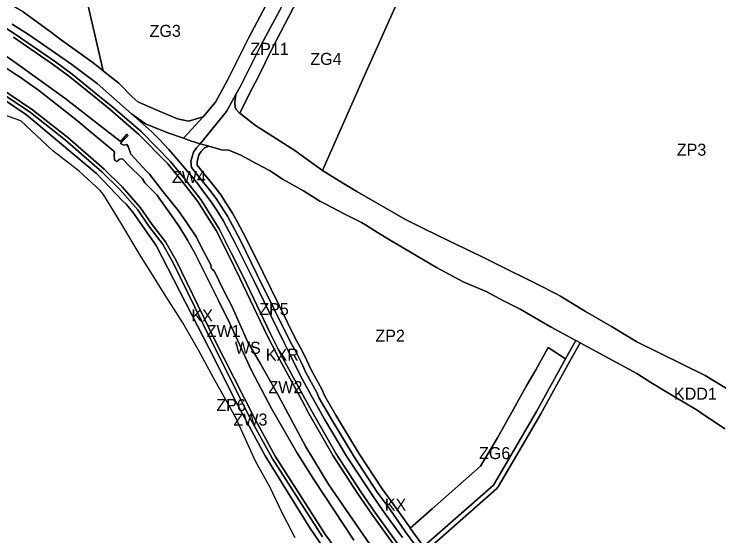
# Model space of a CAD drawing. Extents: x -297419 to -295590, y 31782 to 32981.
# Drawn here: x -296966 to -296379, y 32210 to 32644 of the extents above; entities that cross this region are included whole.
import ezdxf

# ---------------------------------------------------------------- set-up
doc = ezdxf.new("R2010")
doc.units = 0
doc.layers.add('linie_rozgraniczajace', color=7, linetype='Continuous')
doc.layers.add('oznaczenia_przeznaczen', color=7, linetype='Continuous')

msp = doc.modelspace()

# ---------------------------------------------------------------- linework, layer by layer
at = {"layer": 'linie_rozgraniczajace'}
for points in [[(-296976.44, 32861.62), (-296954.158, 32868.81), (-296944.683, 32827.94), (-296939.922, 32807.258), (-296932.119, 32773.36), (-296931.995, 32772.823), (-296926.966, 32750.975), (-296918.118, 32712.537), (-296891.531, 32597.037), (-296894.697, 32599.518), (-296901.08, 32604.52), (-296925.488, 32622.081), (-296927.25, 32623.39), (-296934.691, 32628.923), (-296957.75, 32645.71), (-296964.522, 32649.843), (-296968.384, 32652.199)], [(-296756.167, 32651.476), (-296770.737, 32624.238), (-296788.254, 32589.203), (-296798.128, 32570.931), (-296808.381, 32558.868), (-296820.475, 32555.248), (-296829.819, 32557.158), (-296845.48, 32563.71), (-296860.2, 32570.14), (-296862.84, 32571.4), (-296867.53, 32575.43), (-296878.57, 32586.88), (-296888.438, 32594.613), (-296891.531, 32597.037), (-296918.118, 32712.537)], [(-296362.44, 32326.55), (-296390.75, 32343.51), (-296447.62, 32371.53), (-296468.7, 32384.54), (-296490.15, 32396.76), (-296510.95, 32409.64), (-296514, 32411.185), (-296530.55, 32419.57), (-296562.45, 32435.41), (-296577.24, 32442.8), (-296603.9, 32455.7), (-296625.168, 32466.016), (-296640.53, 32473.71), (-296680.41, 32496.56), (-296691.574, 32503.211), (-296709.14, 32514.16), (-296675.16, 32590.56), (-296634.187, 32682.543)], [(-296744.618, 32647.626), (-296760.078, 32618.724), (-296777.535, 32583.808), (-296781.079, 32577.235), (-296788.984, 32563.16), (-296810.821, 32536.449), (-296818.119, 32538.537), (-296824.845, 32540.945), (-296808.381, 32558.868), (-296798.128, 32570.931), (-296788.254, 32589.203), (-296770.737, 32624.238), (-296756.167, 32651.476)], [(-296957.75, 32645.71), (-296934.691, 32628.923), (-296927.25, 32623.39), (-296925.488, 32622.081), (-296901.08, 32604.52), (-296894.697, 32599.518), (-296891.531, 32597.037), (-296888.438, 32594.613), (-296878.57, 32586.88), (-296867.53, 32575.43), (-296862.84, 32571.4), (-296860.2, 32570.14), (-296845.48, 32563.71), (-296829.819, 32557.158), (-296820.475, 32555.248), (-296808.381, 32558.868), (-296824.845, 32540.945), (-296837.731, 32545.558), (-296856.37, 32553.057), (-296868.02, 32561.4), (-296896.58, 32586.45), (-296917.7, 32602.32), (-296941.1, 32618.6), (-296953.84, 32627.24), (-296967.38, 32635.97)], [(-296646.165, 32203.209), (-296665.589, 32230.008), (-296677.227, 32246.762), (-296697.671, 32278.496), (-296717.798, 32313.354), (-296723.674, 32324.631), (-296743.675, 32361.05), (-296752.326, 32378.33), (-296775.102, 32426.026), (-296784.992, 32445.807), (-296794.94, 32465.703), (-296804.755, 32481.127), (-296810.39, 32489.981), (-296824.182, 32507.725), (-296835.451, 32521.617), (-296860.077, 32546.649), (-296883.508, 32566.906), (-296895.893, 32576.912), (-296917.46, 32594.338), (-296931.299, 32604.419), (-296964.677, 32627.527), (-296979.731, 32637)], [(-296979.731, 32637), (-296964.677, 32627.527), (-296931.299, 32604.419), (-296917.46, 32594.338), (-296895.893, 32576.912), (-296883.508, 32566.906), (-296860.077, 32546.649), (-296835.451, 32521.617), (-296824.182, 32507.725), (-296810.39, 32489.981), (-296804.755, 32481.127), (-296794.94, 32465.703), (-296784.992, 32445.807), (-296775.102, 32426.026), (-296752.326, 32378.33), (-296743.675, 32361.05), (-296723.674, 32324.631), (-296717.798, 32313.354), (-296697.671, 32278.496), (-296677.227, 32246.762), (-296665.589, 32230.008), (-296646.165, 32203.209)], [(-296967.38, 32635.97), (-296953.84, 32627.24), (-296941.1, 32618.6), (-296917.7, 32602.32), (-296896.58, 32586.45), (-296868.02, 32561.4), (-296853.82, 32548.89), (-296851.37, 32546.561), (-296844.87, 32540.28), (-296836.92, 32531.64), (-296825.29, 32518.08), (-296813.71, 32504.11), (-296806.86, 32495.16), (-296801.72, 32488.08), (-296796.66, 32480.63), (-296791.82, 32472.68), (-296781.88, 32453.75), (-296766.15, 32422.74), (-296753.13, 32395.9), (-296740.79, 32370.33), (-296736.62, 32362.06), (-296727.35, 32343.5), (-296719.17, 32328.01), (-296707.31, 32307.22), (-296689.12, 32276.56), (-296664.353, 32239.292), (-296656.947, 32228.497), (-296645.682, 32213.119), (-296642.579, 32208.932)], [(-296966.331, 32625.023), (-296933.037, 32601.973), (-296919.287, 32591.957), (-296897.778, 32574.579), (-296885.433, 32564.604), (-296862.131, 32544.458), (-296837.69, 32519.616), (-296826.531, 32505.859), (-296812.846, 32488.252), (-296807.286, 32479.516), (-296797.554, 32464.223), (-296787.676, 32444.466), (-296777.797, 32424.708), (-296755.021, 32377.012), (-296746.332, 32359.656), (-296726.319, 32323.216), (-296720.428, 32311.91), (-296700.232, 32276.933), (-296679.721, 32245.094), (-296668.036, 32228.272), (-296648.571, 32201.417)], [(-296648.571, 32201.417), (-296668.036, 32228.272), (-296679.721, 32245.094), (-296700.232, 32276.933), (-296720.428, 32311.91), (-296726.319, 32323.216), (-296746.332, 32359.656), (-296755.021, 32377.012), (-296777.797, 32424.708), (-296787.676, 32444.466), (-296797.554, 32464.223), (-296807.286, 32479.516), (-296812.846, 32488.252), (-296826.531, 32505.859), (-296837.69, 32519.616), (-296862.131, 32544.458), (-296885.433, 32564.604), (-296897.778, 32574.579), (-296919.287, 32591.957), (-296933.037, 32601.973), (-296966.331, 32625.023)], [(-296979.7, 32614.244), (-296963.992, 32603.349), (-296923.496, 32574.312), (-296889.742, 32547.865), (-296877.351, 32538.498), (-296876.147, 32539.441), (-296871.887, 32544.352), (-296870.704, 32543.326), (-296875.822, 32538.368), (-296876.433, 32537.776), (-296877.221, 32536.547), (-296874.513, 32535.156), (-296872.017, 32535.831), (-296870.683, 32534.238), (-296868.7, 32527.668), (-296855.755, 32513.911), (-296853.14, 32511.131), (-296841.575, 32496.544), (-296828.794, 32480.705), (-296821.867, 32470.493), (-296814.061, 32458.622), (-296810.256, 32451.223), (-296801.67, 32435.238), (-296801.941, 32434.181), (-296800.499, 32431.303), (-296799.556, 32431.205), (-296790.775, 32413.513), (-296784.189, 32400.682), (-296771.537, 32371.883), (-296760.707, 32353.345), (-296746.366, 32327.729), (-296722.887, 32284.284), (-296703.71, 32252.679), (-296670.068, 32203.65)], [(-296670.068, 32203.65), (-296703.71, 32252.679), (-296722.887, 32284.284), (-296746.366, 32327.729), (-296760.707, 32353.345), (-296771.537, 32371.883), (-296784.189, 32400.682), (-296790.775, 32413.513), (-296799.556, 32431.205), (-296800.499, 32431.303), (-296801.941, 32434.181), (-296801.67, 32435.238), (-296810.256, 32451.223), (-296814.061, 32458.622), (-296821.867, 32470.493), (-296828.794, 32480.705), (-296841.575, 32496.544), (-296853.14, 32511.131), (-296855.755, 32513.911), (-296868.7, 32527.668), (-296870.683, 32534.238), (-296872.017, 32535.831), (-296874.513, 32535.156), (-296877.221, 32536.547), (-296876.433, 32537.776), (-296875.822, 32538.368), (-296870.704, 32543.326), (-296871.887, 32544.352), (-296876.147, 32539.441), (-296877.351, 32538.498), (-296889.742, 32547.865), (-296923.496, 32574.312), (-296963.992, 32603.349), (-296979.7, 32614.244)], [(-296694.342, 32194.502), (-296706.643, 32211.054), (-296730.709, 32248.724), (-296748.443, 32276.481), (-296766.053, 32308.581), (-296799.127, 32374.145), (-296812.592, 32401.695), (-296830.965, 32439.291), (-296839.843, 32454.739), (-296851.191, 32469.491), (-296860.484, 32483.175), (-296875.558, 32500.298), (-296890.705, 32515.225), (-296921.073, 32541.568), (-296950.342, 32564.691), (-296997.759, 32596.595)], [(-296997.759, 32596.595), (-296950.342, 32564.691), (-296921.073, 32541.568), (-296890.705, 32515.225), (-296875.558, 32500.298), (-296860.484, 32483.175), (-296851.191, 32469.491), (-296839.843, 32454.739), (-296830.965, 32439.291), (-296812.592, 32401.695), (-296799.127, 32374.145), (-296766.053, 32308.581), (-296748.443, 32276.481), (-296730.709, 32248.724), (-296706.643, 32211.054), (-296694.342, 32194.502)], [(-296903.987, 32548.085), (-296913.049, 32555.48), (-296938.966, 32575.968), (-296945.263, 32580.972), (-296952.753, 32586.184), (-296961.537, 32592.263), (-296965.131, 32594.622), (-296972.482, 32599.629)], [(-296972.482, 32599.629), (-296965.131, 32594.622), (-296961.537, 32592.263), (-296952.753, 32586.184), (-296945.263, 32580.972), (-296938.966, 32575.968), (-296913.049, 32555.48), (-296903.987, 32548.085), (-296887.59, 32534.3), (-296882.698, 32530.239), (-296882.234, 32529.374), (-296882.353, 32527.237), (-296882.107, 32522.806), (-296880.203, 32521.685), (-296877.784, 32523.552), (-296875.635, 32523.782), (-296870.593, 32518.457), (-296858.821, 32507.292), (-296857.003, 32503.783), (-296853.835, 32500.806), (-296851.547, 32498.563), (-296846.542, 32493.615), (-296844.34, 32490.379), (-296834.598, 32476.753), (-296827.911, 32466.774), (-296821.393, 32456.15), (-296815.494, 32446.001), (-296796.259, 32407.061), (-296786.235, 32386.815), (-296768.036, 32347.909), (-296751.391, 32316.324), (-296730.434, 32279.724), (-296716.319, 32257.025), (-296682.955, 32206.55)], [(-296999.388, 32594.075), (-296952.112, 32562.266), (-296922.986, 32539.257), (-296892.743, 32513.021), (-296877.74, 32498.235), (-296862.86, 32481.334), (-296853.623, 32467.732), (-296842.344, 32453.07), (-296833.616, 32437.884), (-296815.287, 32400.378), (-296801.815, 32372.811), (-296768.708, 32307.183), (-296751.025, 32274.951), (-296733.238, 32247.109), (-296709.114, 32209.35)], [(-296709.114, 32209.35), (-296733.238, 32247.109), (-296751.025, 32274.951), (-296768.708, 32307.183), (-296801.815, 32372.811), (-296815.287, 32400.378), (-296833.616, 32437.884), (-296842.344, 32453.07), (-296853.623, 32467.732), (-296862.86, 32481.334), (-296877.74, 32498.235), (-296892.743, 32513.021), (-296922.986, 32539.257), (-296952.112, 32562.266), (-296999.388, 32594.075)], [(-296996.6, 32588.21), (-296956.31, 32561.08), (-296953.776, 32558.972), (-296928, 32537.52), (-296897.27, 32511.62), (-296875.179, 32488.725), (-296872.51, 32486.08), (-296866.97, 32479.53), (-296847.58, 32451.73), (-296803.26, 32365.99), (-296781.55, 32322.47), (-296756.9, 32276.76), (-296719.6, 32217.08), (-296700.61, 32188.99)], [(-296700.61, 32188.99), (-296719.6, 32217.08), (-296756.9, 32276.76), (-296781.55, 32322.47), (-296803.26, 32365.99), (-296847.58, 32451.73), (-296866.97, 32479.53), (-296872.51, 32486.08), (-296875.179, 32488.725), (-296897.27, 32511.62), (-296928, 32537.52), (-296953.776, 32558.972), (-296956.31, 32561.08), (-296996.6, 32588.21)], [(-296374.24, 32299.4), (-296394.44, 32312.98), (-296397.416, 32314.751), (-296424.062, 32330.514), (-296435.806, 32337.962), (-296447.55, 32345.41), (-296494.83, 32370.91), (-296498.355, 32372.801), (-296518.695, 32383.711), (-296544.62, 32398.85), (-296557.817, 32405.549), (-296572.89, 32413.46), (-296592.12, 32421.52), (-296614.14, 32433.58), (-296652.724, 32456.188), (-296663.209, 32462.514), (-296673.427, 32469.046), (-296676.747, 32470.782), (-296690.52, 32477.86), (-296706.981, 32486.44), (-296711.26, 32488.67), (-296724.99, 32497.22), (-296741.7, 32506.77), (-296753.12, 32514.09), (-296764.31, 32520.1), (-296777.12, 32526.87), (-296786.9, 32531.07), (-296793.139, 32531.392), (-296803.709, 32534.415), (-296810.821, 32536.449), (-296788.984, 32563.16), (-296781.079, 32577.235), (-296782.064, 32570.68), (-296781.704, 32566.441), (-296780.654, 32564.479), (-296778.499, 32562.184), (-296777.942, 32561.747), (-296764.83, 32551.46), (-296744.291, 32538.492), (-296732.02, 32530.79), (-296723.08, 32524.03), (-296709.14, 32514.16), (-296691.574, 32503.211), (-296680.41, 32496.56), (-296640.53, 32473.71), (-296625.168, 32466.016), (-296603.9, 32455.7), (-296577.24, 32442.8), (-296562.45, 32435.41), (-296530.55, 32419.57), (-296514, 32411.185), (-296510.95, 32409.64), (-296490.15, 32396.76), (-296468.7, 32384.54), (-296447.62, 32371.53), (-296390.75, 32343.51), (-296362.44, 32326.55)], [(-296731.83, 32208.6), (-296742.31, 32228.86), (-296752.59, 32250.4), (-296764.79, 32272.44), (-296780.64, 32307.22), (-296787.11, 32319.05), (-296799.85, 32341.69), (-296812.3, 32364.77), (-296825.39, 32387.55), (-296833.1, 32399.52), (-296840.03, 32410.55), (-296850.59, 32427.25), (-296860.06, 32442.35), (-296876.78, 32470.6), (-296891.23, 32494.12), (-296894.12, 32497.43), (-296911.59, 32513.59), (-296933.39, 32530.65), (-296960.04, 32555.36), (-296990.35, 32566.02)], [(-296642.579, 32208.932), (-296645.682, 32213.119), (-296656.947, 32228.497), (-296664.353, 32239.292), (-296689.12, 32276.56), (-296707.31, 32307.22), (-296719.17, 32328.01), (-296727.35, 32343.5), (-296736.62, 32362.06), (-296740.79, 32370.33), (-296753.13, 32395.9), (-296766.15, 32422.74), (-296781.88, 32453.75), (-296791.82, 32472.68), (-296796.66, 32480.63), (-296801.72, 32488.08), (-296806.86, 32495.16), (-296813.71, 32504.11), (-296825.29, 32518.08), (-296836.92, 32531.64), (-296844.87, 32540.28), (-296851.37, 32546.561), (-296853.82, 32548.89), (-296868.02, 32561.4), (-296856.37, 32553.057), (-296837.731, 32545.558), (-296824.845, 32540.945), (-296818.119, 32538.537), (-296810.821, 32536.449), (-296810.834, 32536.433), (-296814.004, 32533.133), (-296816.473, 32529.357), (-296818.326, 32522.673), (-296818.556, 32521.843), (-296818.101, 32516.592), (-296810.511, 32507.208), (-296804.285, 32499.47), (-296797.672, 32490.937), (-296793.22, 32483.862), (-296788.209, 32476.139), (-296784.239, 32468.853), (-296777.282, 32455.872), (-296763.349, 32427.307), (-296735.724, 32371.365), (-296730.62, 32362.481), (-296726.939, 32354.612), (-296722.942, 32346.058), (-296714.216, 32330.141), (-296711.916, 32324.823), (-296702.253, 32308.033), (-296682.71, 32275.902), (-296663.514, 32246.531), (-296653.68, 32233.27), (-296640.249, 32214.007), (-296628.751, 32198.069)], [(-296682.955, 32206.55), (-296716.319, 32257.025), (-296730.434, 32279.724), (-296751.391, 32316.324), (-296768.036, 32347.909), (-296786.235, 32386.815), (-296796.259, 32407.061), (-296815.494, 32446.001), (-296821.393, 32456.15), (-296827.911, 32466.774), (-296834.598, 32476.753), (-296844.34, 32490.379), (-296846.542, 32493.615), (-296851.547, 32498.563), (-296853.835, 32500.806), (-296857.003, 32503.783), (-296858.821, 32507.292), (-296870.593, 32518.457), (-296875.635, 32523.782), (-296877.784, 32523.552), (-296880.203, 32521.685), (-296882.107, 32522.806), (-296882.353, 32527.237), (-296882.234, 32529.374), (-296882.698, 32530.239), (-296887.59, 32534.3), (-296903.987, 32548.085)], [(-296818.556, 32521.843), (-296818.326, 32522.673), (-296816.473, 32529.357), (-296814.004, 32533.133), (-296810.834, 32536.433), (-296810.821, 32536.449), (-296803.709, 32534.415), (-296807.228, 32532.97), (-296810.075, 32530.006), (-296811.862, 32527.272), (-296813.497, 32521.376), (-296813.251, 32518.547), (-296806.615, 32510.343), (-296800.361, 32502.569), (-296793.72, 32494), (-296789.01, 32486.56), (-296783.91, 32478.7), (-296779.84, 32471.23), (-296772.83, 32458.15), (-296758.86, 32429.51), (-296731.31, 32373.72), (-296726.18, 32364.79), (-296722.41, 32356.73), (-296718.48, 32348.32), (-296709.72, 32332.34), (-296707.44, 32327.07), (-296697.95, 32310.58), (-296678.48, 32278.57), (-296659.41, 32249.39), (-296649.62, 32236.19), (-296636.17, 32216.9), (-296636.097, 32216.799), (-296624.981, 32201.389), (-296566.937, 32252.512), (-296566.047, 32253.693), (-296554.264, 32273.86), (-296530.986, 32313.692), (-296506.9, 32357.447), (-296498.355, 32372.801), (-296494.83, 32370.91), (-296503.4, 32355.51), (-296527.507, 32311.718), (-296550.81, 32271.842), (-296562.712, 32251.472), (-296563.988, 32249.779), (-296622.63, 32198.13)], [(-296726.939, 32354.612), (-296730.62, 32362.481), (-296735.724, 32371.365), (-296763.349, 32427.307), (-296777.282, 32455.872), (-296784.239, 32468.853), (-296788.209, 32476.139), (-296793.22, 32483.862), (-296797.672, 32490.937), (-296804.285, 32499.47), (-296810.511, 32507.208), (-296818.101, 32516.592), (-296818.556, 32521.843)], [(-296622.63, 32198.13), (-296563.988, 32249.779), (-296562.712, 32251.472), (-296550.81, 32271.842), (-296527.507, 32311.718), (-296503.4, 32355.51), (-296494.83, 32370.91), (-296447.55, 32345.41), (-296435.806, 32337.962), (-296424.062, 32330.514), (-296397.416, 32314.751), (-296394.44, 32312.98), (-296374.24, 32299.4)], [(-296628.751, 32198.069), (-296640.249, 32214.007), (-296653.68, 32233.27), (-296663.514, 32246.531), (-296682.71, 32275.902), (-296702.253, 32308.033), (-296711.916, 32324.823), (-296714.216, 32330.141), (-296722.942, 32346.058), (-296726.939, 32354.612)]]:
    msp.add_lwpolyline(points, dxfattribs=at)
for points in [[(-296777.942, 32561.747), (-296770.175, 32577.711), (-296762.656, 32591.889), (-296751.061, 32615.649), (-296726.519, 32662.78), (-296725.507, 32662.314), (-296722.974, 32662.16), (-296720.792, 32664.118), (-296718.063, 32666.063), (-296713.933, 32669.007), (-296710.323, 32670.884), (-296699.971, 32674.738), (-296692.073, 32677.65), (-296666.705, 32685.467), (-296659.408, 32686.233), (-296645.164, 32685.272), (-296639.959, 32684.125), (-296634.187, 32682.543), (-296675.16, 32590.56), (-296709.14, 32514.16), (-296723.08, 32524.03), (-296732.02, 32530.79), (-296744.291, 32538.492), (-296764.83, 32551.46)], [(-296782.064, 32570.68), (-296781.079, 32577.235), (-296777.535, 32583.808), (-296760.078, 32618.724), (-296744.618, 32647.626), (-296734.893, 32666.637), (-296729.247, 32664.037), (-296726.519, 32662.78), (-296751.061, 32615.649), (-296762.656, 32591.889), (-296770.175, 32577.711), (-296777.942, 32561.747), (-296778.499, 32562.184), (-296780.654, 32564.479), (-296781.704, 32566.441)], [(-296813.497, 32521.376), (-296811.862, 32527.272), (-296810.075, 32530.006), (-296807.228, 32532.97), (-296803.709, 32534.415), (-296793.139, 32531.392), (-296786.9, 32531.07), (-296777.12, 32526.87), (-296764.31, 32520.1), (-296753.12, 32514.09), (-296741.7, 32506.77), (-296724.99, 32497.22), (-296711.26, 32488.67), (-296706.981, 32486.44), (-296690.52, 32477.86), (-296676.747, 32470.782), (-296673.427, 32469.046), (-296663.209, 32462.514), (-296652.724, 32456.188), (-296614.14, 32433.58), (-296592.12, 32421.52), (-296572.89, 32413.46), (-296557.817, 32405.549), (-296544.62, 32398.85), (-296518.695, 32383.711), (-296498.355, 32372.801), (-296506.9, 32357.447), (-296521.27, 32366.92), (-296531.55, 32348.39), (-296539.01, 32335.5), (-296550.24, 32315.54), (-296563.4, 32291.74), (-296574.16, 32273.74), (-296577.49, 32268.15), (-296617.9, 32232.78), (-296636.097, 32216.799), (-296636.17, 32216.9), (-296649.62, 32236.19), (-296659.41, 32249.39), (-296678.48, 32278.57), (-296697.95, 32310.58), (-296707.44, 32327.07), (-296709.72, 32332.34), (-296718.48, 32348.32), (-296722.41, 32356.73), (-296726.18, 32364.79), (-296731.31, 32373.72), (-296758.86, 32429.51), (-296772.83, 32458.15), (-296779.84, 32471.23), (-296783.91, 32478.7), (-296789.01, 32486.56), (-296793.72, 32494), (-296800.361, 32502.569), (-296806.615, 32510.343), (-296813.251, 32518.547)], [(-296636.097, 32216.799), (-296617.9, 32232.78), (-296577.49, 32268.15), (-296574.16, 32273.74), (-296563.4, 32291.74), (-296550.24, 32315.54), (-296539.01, 32335.5), (-296531.55, 32348.39), (-296521.27, 32366.92), (-296506.9, 32357.447), (-296530.986, 32313.692), (-296554.264, 32273.86), (-296566.047, 32253.693), (-296566.937, 32252.512), (-296624.981, 32201.389)]]:
    msp.add_lwpolyline(points, close=True, dxfattribs=at)

# ---------------------------------------------------------------- texts
at = {"layer": 'oznaczenia_przeznaczen'}
for s, p in [('ZG3', (-296852.950411, 32625.285001)), ('ZP11', (-296769.182223, 32610.346001)), ('ZG4', (-296719.219893, 32602.010001)), ('ZP3', (-296414.294351, 32526.453001)), ('ZW4', (-296834.3236, 32503.795451)), ('ZP5', (-296761.715846, 32393.853957)), ('KX', (-296818.095718, 32388.593407)), ('ZW1', (-296805.436626, 32375.671418)), ('ZP2', (-296665.087536, 32371.709001)), ('WS', (-296781.948588, 32361.694261)), ('KXR', (-296756.272668, 32355.929066)), ('ZW2', (-296754.025797, 32328.938166)), ('KDD1', (-296416.625882, 32323.517001)), ('ZP6', (-296797.405148, 32314.050001)), ('ZW3', (-296783.147259, 32302.023728)), ('ZG6', (-296578.862208, 32274.113001)), ('KX', (-296657.256869, 32231.190001))]:
    msp.add_text(s, height=10, dxfattribs=at).set_placement(p)

doc.saveas('drawing.dxf')
